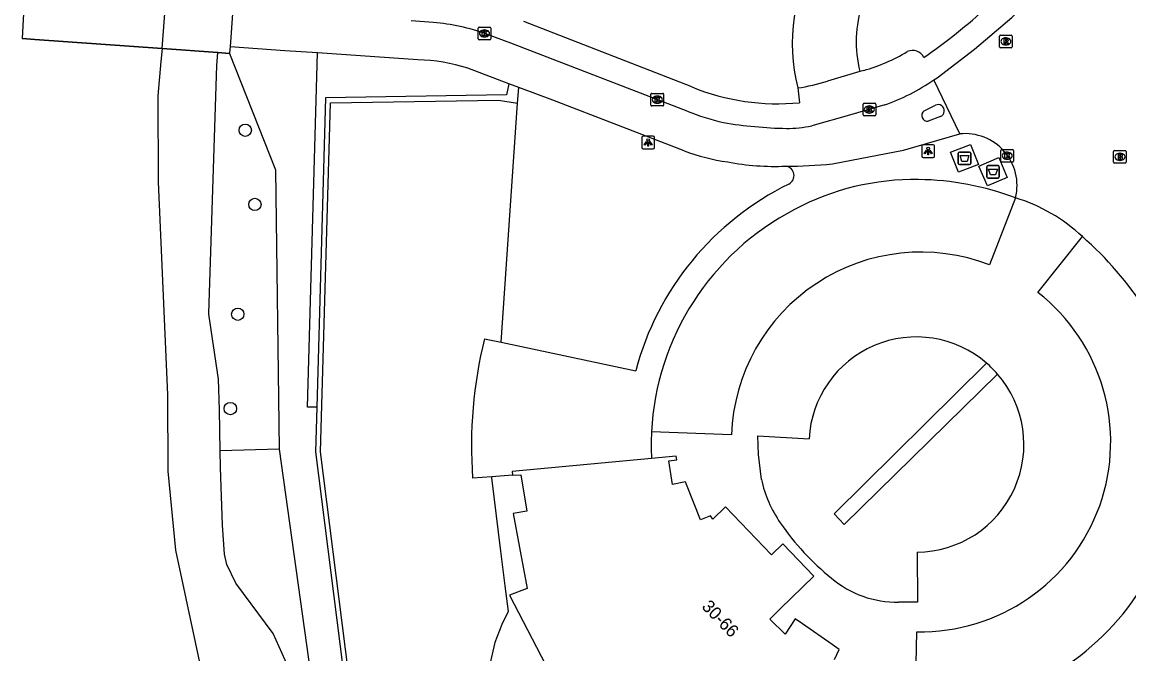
# Model space of a CAD drawing. Extents: x 159040 to 160094, y 381214 to 382518.
# Drawn here: x 159039.5 to 159127.2, y 381279.5 to 381329.5 of the extents above; entities that cross this region are included whole.
import ezdxf

# ---------------------------------------------------------------- set-up
doc = ezdxf.new("R2010")
doc.units = 0
for name, color, linetype in [('IMGEO_Afval_apart_plaats', 7, 'Continuous'), ('IMGEO_Boom', 7, 'Continuous'), ('IMGEO_Brandkraan', 7, 'Continuous'), ('IMGEO_Dek', 7, 'Continuous'), ('IMGEO_Fietspad_gesloten', 7, 'Continuous'), ('IMGEO_Fietspad_open', 7, 'Continuous'), ('IMGEO_Groenvoorziening', 7, 'Continuous'), ('IMGEO_Haag', 7, 'Continuous'), ('IMGEO_Hek', 7, 'Continuous'), ('IMGEO_Kolk', 7, 'Continuous'), ('IMGEO_Lichtpunt', 7, 'Continuous'), ('IMGEO_Pand', 7, 'Continuous'), ('IMGEO_Pand_nummerreeks', 7, 'Continuous'), ('IMGEO_Parkeervlak_open', 7, 'Continuous'), ('IMGEO_Rijbaan_lokaal_open', 7, 'Continuous'), ('IMGEO_Rioolput', 7, 'Continuous'), ('IMGEO_Voetpad_gesloten', 7, 'Continuous'), ('IMGEO_Voetpad_open', 7, 'Continuous'), ('IMGEO_Waterloop', 7, 'Continuous')]:
    doc.layers.add(name, color=color, linetype=linetype)

msp = doc.modelspace()

# ---------------------------------------------------------------- linework, layer by layer
at = {"layer": 'IMGEO_Afval_apart_plaats'}
for p, q in [((159113.713, 381318.326), (159113.713, 381319.126)), ((159113.713, 381319.126), (159113.713, 381318.326)), ((159113.813, 381319.226), (159114.603, 381319.226)), ((159114.603, 381319.226), (159113.813, 381319.226)), ((159114.703, 381319.126), (159114.703, 381318.326)), ((159114.703, 381318.326), (159114.703, 381319.126)), ((159114.603, 381318.226), (159113.813, 381318.226)), ((159113.813, 381318.226), (159114.603, 381318.226)), ((159115.976, 381317.265), (159115.976, 381318.065)), ((159115.976, 381318.065), (159115.976, 381317.265)), ((159116.076, 381318.165), (159116.866, 381318.165)), ((159116.866, 381318.165), (159116.076, 381318.165)), ((159116.966, 381318.065), (159116.966, 381317.265)), ((159116.966, 381317.265), (159116.966, 381318.065)), ((159116.866, 381317.165), (159116.076, 381317.165)), ((159116.076, 381317.165), (159116.866, 381317.165))]:
    msp.add_line(p, q, dxfattribs=at)
for points in [[(159113.856, 381318.94), (159114.56, 381318.94), (159114.411, 381318.47), (159114.005, 381318.47), (159113.856, 381318.94)], [(159116.119, 381317.879), (159116.823, 381317.879), (159116.674, 381317.409), (159116.268, 381317.409), (159116.119, 381317.879)]]:
    msp.add_lwpolyline(points, dxfattribs=at)
for centre, start, end in [((159113.813, 381319.126), 90, 180), ((159113.813, 381319.126), 90, 180), ((159114.603, 381319.126), 0, 90), ((159114.603, 381319.126), 360, 90), ((159113.813, 381318.326), 180, 270), ((159113.813, 381318.326), 180, 270), ((159114.603, 381318.326), 270, 0), ((159114.603, 381318.326), 270, 0), ((159116.076, 381318.065), 90, 180), ((159116.076, 381318.065), 90, 180), ((159116.866, 381318.065), 0, 90), ((159116.866, 381318.065), 360, 90), ((159116.076, 381317.265), 180, 270), ((159116.076, 381317.265), 180, 270), ((159116.866, 381317.265), 270, 0), ((159116.866, 381317.265), 270, 0)]:
    msp.add_arc(centre, 0.1, start, end, dxfattribs=at)
at = {"layer": 'IMGEO_Boom'}
for centre in [(159057.207, 381320.956), (159057.971, 381315.075), (159056.615, 381306.375), (159056.023, 381298.901)]:
    msp.add_circle(centre, 0.489, dxfattribs=at)
at = {"layer": 'IMGEO_Brandkraan'}
for p, q in [((159126.028, 381318.418), (159126.028, 381319.27)), ((159126.103, 381319.344), (159126.955, 381319.344)), ((159126.516, 381319.124), (159126.541, 381319.124)), ((159127.029, 381319.27), (159127.029, 381318.418)), ((159126.955, 381318.344), (159126.103, 381318.344)), ((159126.539, 381318.564), (159126.514, 381318.564))]:
    msp.add_line(p, q, dxfattribs=at)
for points in [[(159126.028, 381318.418), (159126.028, 381319.27)], [(159126.103, 381319.344), (159126.955, 381319.344)], [(159126.376, 381319.044), (159126.376, 381318.644), (159126.589, 381318.644)], [(159126.607, 381319.044), (159126.376, 381319.044)], [(159126.555, 381318.963), (159126.501, 381318.963), (159126.501, 381318.887)], [(159127.029, 381319.27), (159127.029, 381318.418)], [(159126.955, 381318.344), (159126.103, 381318.344)], [(159126.501, 381318.887), (159126.554, 381318.887)], [(159126.563, 381318.811), (159126.501, 381318.811), (159126.501, 381318.73)], [(159126.501, 381318.73), (159126.563, 381318.73)]]:
    msp.add_lwpolyline(points, dxfattribs=at)
for centre, radius, start, end in [((159126.105, 381319.268), 0.0765, 91.55205, 178.44795), ((159126.105, 381319.268), 0.0765, 91.55205, 178.44795), ((159126.556, 381318.925), 0.0379, 267.82845, 90.93552), ((159126.611, 381318.899), 0.145, 59.4692, 91.53667), ((159126.636, 381318.946), 0.0922, 285.51372, 58.15012), ((159126.953, 381319.268), 0.0765, 1.55205, 88.44795), ((159126.953, 381319.268), 0.0765, 1.55205, 88.44795), ((159126.105, 381318.42), 0.0765, 181.55205, 268.44795), ((159126.105, 381318.42), 0.0765, 181.55205, 268.44795), ((159126.564, 381318.77), 0.0404, 269.87594, 90.50774), ((159126.595, 381318.895), 0.251, 268.66757, 293.53466), ((159126.641, 381318.754), 0.105, 301.31148, 78.98903), ((159126.953, 381318.42), 0.0765, 271.55205, 358.44795), ((159126.953, 381318.42), 0.0765, 271.55205, 358.44795)]:
    msp.add_arc(centre, radius, start, end, dxfattribs=at)
for centre, major_axis, ratio, start_param, end_param in [((159126.515, 381318.844), (-0.387, 0.002), 0.722429, 4.712389, 7.853982), ((159126.54, 381318.844), (-0.39, 0.002), 0.717154, 1.570796, 4.712389)]:
    msp.add_ellipse(centre, major_axis=major_axis, ratio=ratio, start_param=start_param, end_param=end_param, dxfattribs=at)
at = {"layer": 'IMGEO_Dek'}
msp.add_lwpolyline([(159039.522, 381328.211), (159040.528, 381328.139), (159050.61, 381327.415), (159050.884, 381330.878), (159051.05, 381332.975), (159041.35, 381333.612), (159039.813, 381333.713)], close=True, dxfattribs=at)
at = {"layer": 'IMGEO_Fietspad_gesloten'}
for points in [[(159056.213, 381330.56), (159056.002, 381327.557)], [(159072.11, 381329.478), (159070.351, 381329.619)], [(159092.234, 381322.458), (159078.254, 381327.862), (159076.323, 381328.564)], [(159062.942, 381327.072), (159060.335, 381327.254), (159056.002, 381327.557)], [(159070.882, 381326.518), (159062.942, 381327.072)], [(159078.098, 381324.639), (159074.845, 381325.858)], [(159078.875, 381324.348), (159078.098, 381324.639)], [(159091.996, 381319.311), (159081.582, 381323.334), (159078.875, 381324.348)], [(159107.881, 381322.952), (159105.106, 381322.135), (159102.101, 381321.307)], [(159111.006, 381322.488), (159111.903, 381322.937)], [(159112.303, 381322.03), (159111.34, 381321.673)], [(159103.746, 381318.292), (159103.883, 381318.313), (159109.374, 381319.367), (159113.837, 381320.659)]]:
    msp.add_lwpolyline(points, dxfattribs=at)
for centre, radius, start, end in [((159071.003, 381314.209), 15.309, 69.66557, 85.85345), ((159070.726, 381313.351), 13.168, 71.76989, 89.31953), ((159102.403, 381338.407), 16.397, 289.51725, 304.82163), ((159099.562, 381340.778), 19.731, 248.19782, 256.95343), ((159111.27, 381322.12), 0.453, 125.6821, 278.8871), ((159112.113, 381322.488), 0.496, 292.59622, 115.00011), ((159100.793, 381356.007), 34.917, 260.62895, 268.85376), ((159100.161, 381330.154), 9.057, 269.58337, 282.36922), ((159097.909, 381335.419), 17.159, 249.84291, 261.74079), ((159099.198, 381338.512), 20.422, 259.40818, 272.33536), ((159100.221, 381351.676), 33.569, 269.67333, 276.02687)]:
    msp.add_arc(centre, radius, start, end, dxfattribs=at)
at = {"layer": 'IMGEO_Fietspad_open'}
for points in [[(159050.61, 381327.415), (159050.884, 381330.878)], [(159055.038, 381327.097), (159050.61, 381327.415)], [(159055.965, 381327.03), (159055.038, 381327.097)], [(159056.002, 381327.557), (159055.968, 381327.077), (159055.965, 381327.03)]]:
    msp.add_lwpolyline(points, dxfattribs=at)
at = {"layer": 'IMGEO_Groenvoorziening'}
for points in [[(159055.225, 381295.548), (159055.17, 381298.792), (159055.072, 381301.237), (159054.306, 381306.385), (159054.307, 381306.436), (159054.944, 381326.09), (159055.038, 381327.097)], [(159055.965, 381327.03), (159059.596, 381317.823), (159059.886, 381295.701)], [(159062.871, 381299.017), (159062.144, 381299.013), (159062.942, 381327.072)], [(159077.474, 381304.155), (159078.788, 381323.092)], [(159059.886, 381295.701), (159055.225, 381295.548)], [(159064.372, 381231.439), (159063.173, 381244.5), (159063.456, 381245.743), (159064.371, 381248.141), (159064.814, 381250.033), (159064.541, 381252.253), (159063.389, 381262.097), (159061.869, 381273.046), (159060.845, 381277.924), (159059.418, 381281.101), (159056.47, 381285.076), (159055.747, 381286.553), (159055.558, 381287.374), (159055.393, 381289.669), (159055.248, 381294.247), (159055.225, 381295.548)], [(159059.886, 381295.701), (159069.218, 381228.972)], [(159076.735, 381293.506), (159076.728, 381293.411), (159077.446, 381287.606), (159077.786, 381284.859), (159078.036, 381282.835), (159077.536, 381281.814), (159076.998, 381280.371), (159076.605, 381278.761), (159076.401, 381276.883), (159076.43, 381275.338), (159076.767, 381273.19), (159077.261, 381271.58), (159077.809, 381270.321), (159078.666, 381268.84), (159079.964, 381267.184), (159084.27, 381233.151)]]:
    msp.add_lwpolyline(points, dxfattribs=at)
at = {"layer": 'IMGEO_Haag'}
for points in [[(159078.098, 381324.639), (159077.92, 381323.747), (159063.568, 381323.527), (159062.871, 381299.017)], [(159078.788, 381323.092), (159078.875, 381324.348)], [(159084.27, 381233.151), (159071.09, 381232.965), (159063.171, 381295.487), (159063.957, 381323.133), (159077.281, 381323.321), (159078.788, 381323.092)], [(159062.871, 381299.017), (159062.77, 381295.468), (159070.738, 381232.56), (159071.355, 381232.569)]]:
    msp.add_lwpolyline(points, dxfattribs=at)
at = {"layer": 'IMGEO_Hek'}
for points in [[(159040.528, 381328.139), (159039.522, 381328.211)], [(159050.61, 381327.415), (159040.528, 381328.139)], [(159050.61, 381327.415), (159055.038, 381327.097)], [(159055.038, 381327.097), (159055.965, 381327.03)]]:
    msp.add_lwpolyline(points, dxfattribs=at)
at = {"layer": 'IMGEO_Kolk'}
for p, q in [((159075.663, 381328.195), (159075.663, 381329.047)), ((159075.738, 381329.121), (159076.59, 381329.121)), ((159076.151, 381328.901), (159076.176, 381328.901)), ((159076.664, 381329.047), (159076.664, 381328.195)), ((159076.59, 381328.121), (159075.738, 381328.121)), ((159076.174, 381328.341), (159076.149, 381328.341)), ((159089.361, 381322.948), (159089.361, 381323.8)), ((159089.436, 381323.874), (159090.288, 381323.874)), ((159089.849, 381323.654), (159089.874, 381323.654)), ((159090.362, 381323.8), (159090.362, 381322.948)), ((159090.288, 381322.874), (159089.436, 381322.874)), ((159089.872, 381323.094), (159089.847, 381323.094)), ((159106.168, 381322.168), (159106.168, 381323.02)), ((159106.243, 381323.094), (159107.095, 381323.094)), ((159106.656, 381322.874), (159106.681, 381322.874)), ((159107.169, 381323.02), (159107.169, 381322.168)), ((159107.095, 381322.094), (159106.243, 381322.094)), ((159106.679, 381322.314), (159106.654, 381322.314)), ((159117.095, 381318.506), (159117.095, 381319.358)), ((159117.17, 381319.432), (159118.022, 381319.432)), ((159117.583, 381319.212), (159117.608, 381319.212)), ((159118.096, 381319.358), (159118.096, 381318.506)), ((159118.022, 381318.432), (159117.17, 381318.432)), ((159117.606, 381318.652), (159117.581, 381318.652))]:
    msp.add_line(p, q, dxfattribs=at)
for points in [[(159075.663, 381328.195), (159075.663, 381329.047)], [(159075.738, 381329.121), (159076.59, 381329.121)], [(159075.984, 381328.821), (159076.107, 381328.821), (159076.107, 381328.67), (159076.237, 381328.821), (159076.401, 381328.821), (159076.255, 381328.67), (159076.408, 381328.421), (159076.256, 381328.421), (159076.171, 381328.585), (159076.107, 381328.518), (159076.107, 381328.421), (159075.984, 381328.421), (159075.984, 381328.821)], [(159076.664, 381329.047), (159076.664, 381328.195)], [(159076.59, 381328.121), (159075.738, 381328.121)], [(159089.361, 381322.948), (159089.361, 381323.8)], [(159089.436, 381323.874), (159090.288, 381323.874)], [(159089.682, 381323.574), (159089.805, 381323.574), (159089.805, 381323.423), (159089.935, 381323.574), (159090.099, 381323.574), (159089.953, 381323.423), (159090.106, 381323.174), (159089.954, 381323.174), (159089.869, 381323.338), (159089.805, 381323.271), (159089.805, 381323.174), (159089.682, 381323.174), (159089.682, 381323.574)], [(159090.362, 381323.8), (159090.362, 381322.948)], [(159090.288, 381322.874), (159089.436, 381322.874)], [(159106.168, 381322.168), (159106.168, 381323.02)], [(159106.243, 381323.094), (159107.095, 381323.094)], [(159106.489, 381322.794), (159106.612, 381322.794), (159106.612, 381322.643), (159106.742, 381322.794), (159106.906, 381322.794), (159106.76, 381322.643), (159106.913, 381322.394), (159106.761, 381322.394), (159106.676, 381322.558), (159106.612, 381322.491), (159106.612, 381322.394), (159106.489, 381322.394), (159106.489, 381322.794)], [(159107.169, 381323.02), (159107.169, 381322.168)], [(159107.095, 381322.094), (159106.243, 381322.094)], [(159117.095, 381318.506), (159117.095, 381319.358)], [(159117.17, 381319.432), (159118.022, 381319.432)], [(159117.416, 381319.132), (159117.539, 381319.132), (159117.539, 381318.981), (159117.669, 381319.132), (159117.833, 381319.132), (159117.687, 381318.981), (159117.84, 381318.732), (159117.688, 381318.732), (159117.603, 381318.896), (159117.539, 381318.829), (159117.539, 381318.732), (159117.416, 381318.732), (159117.416, 381319.132)], [(159118.096, 381319.358), (159118.096, 381318.506)], [(159118.022, 381318.432), (159117.17, 381318.432)]]:
    msp.add_lwpolyline(points, dxfattribs=at)
for centre, start, end in [((159075.74, 381329.045), 91.55205, 178.44795), ((159075.74, 381329.045), 91.55205, 178.44795), ((159076.588, 381329.045), 1.55205, 88.44795), ((159076.588, 381329.045), 1.55205, 88.44795), ((159075.74, 381328.197), 181.55205, 268.44795), ((159075.74, 381328.197), 181.55205, 268.44795), ((159076.588, 381328.197), 271.55205, 358.44795), ((159076.588, 381328.197), 271.55205, 358.44795), ((159089.438, 381323.798), 91.55205, 178.44795), ((159089.438, 381323.798), 91.55205, 178.44795), ((159090.286, 381323.798), 1.55205, 88.44795), ((159090.286, 381323.798), 1.55205, 88.44795), ((159089.438, 381322.95), 181.55205, 268.44795), ((159089.438, 381322.95), 181.55205, 268.44795), ((159090.286, 381322.95), 271.55205, 358.44795), ((159090.286, 381322.95), 271.55205, 358.44795), ((159106.245, 381323.018), 91.55205, 178.44795), ((159106.245, 381323.018), 91.55205, 178.44795), ((159107.093, 381323.018), 1.55205, 88.44795), ((159107.093, 381323.018), 1.55205, 88.44795), ((159106.245, 381322.17), 181.55205, 268.44795), ((159106.245, 381322.17), 181.55205, 268.44795), ((159107.093, 381322.17), 271.55205, 358.44795), ((159107.093, 381322.17), 271.55205, 358.44795), ((159117.172, 381319.356), 91.55205, 178.44795), ((159117.172, 381319.356), 91.55205, 178.44795), ((159118.02, 381319.356), 1.55205, 88.44795), ((159118.02, 381319.356), 1.55205, 88.44795), ((159117.172, 381318.508), 181.55205, 268.44795), ((159117.172, 381318.508), 181.55205, 268.44795), ((159118.02, 381318.508), 271.55205, 358.44795), ((159118.02, 381318.508), 271.55205, 358.44795)]:
    msp.add_arc(centre, 0.0765, start, end, dxfattribs=at)
for centre, major_axis, ratio, start_param, end_param in [((159076.15, 381328.621), (-0.387, 0.002), 0.722429, 4.712389, 7.853982), ((159076.175, 381328.621), (-0.39, 0.002), 0.717154, 1.570796, 4.712389), ((159089.848, 381323.374), (-0.387, 0.002), 0.722429, 4.712389, 7.853982), ((159089.873, 381323.374), (-0.39, 0.002), 0.717154, 1.570796, 4.712389), ((159106.655, 381322.594), (-0.387, 0.002), 0.722429, 4.712389, 7.853982), ((159106.68, 381322.594), (-0.39, 0.002), 0.717154, 1.570796, 4.712389), ((159117.582, 381318.932), (-0.387, 0.002), 0.722429, 4.712389, 7.853982), ((159117.607, 381318.932), (-0.39, 0.002), 0.717154, 1.570796, 4.712389)]:
    msp.add_ellipse(centre, major_axis=major_axis, ratio=ratio, start_param=start_param, end_param=end_param, dxfattribs=at)
at = {"layer": 'IMGEO_Lichtpunt'}
for p, q in [((159088.639, 381320.384), (159088.639, 381319.577)), ((159088.639, 381320.384), (159088.639, 381319.577)), ((159089.541, 381320.479), (159088.733, 381320.479)), ((159089.541, 381320.479), (159088.733, 381320.479)), ((159089.635, 381319.577), (159089.635, 381320.384)), ((159089.635, 381319.577), (159089.635, 381320.384)), ((159111.729, 381319.799), (159110.921, 381319.799)), ((159111.729, 381319.799), (159110.921, 381319.799)), ((159088.733, 381319.483), (159089.541, 381319.483)), ((159088.733, 381319.483), (159089.541, 381319.483)), ((159110.827, 381319.704), (159110.827, 381318.897)), ((159110.827, 381319.704), (159110.827, 381318.897)), ((159111.823, 381318.897), (159111.823, 381319.704)), ((159111.823, 381318.897), (159111.823, 381319.704)), ((159110.921, 381318.803), (159111.729, 381318.803)), ((159110.921, 381318.803), (159111.729, 381318.803))]:
    msp.add_line(p, q, dxfattribs=at)
for points in [[(159089.013, 381320.048), (159089.052, 381320.02), (159088.864, 381319.758), (159088.826, 381319.785), (159089.013, 381320.048)], [(159089.115, 381320), (159089.162, 381320), (159089.162, 381319.678), (159089.115, 381319.678), (159089.115, 381320)], [(159089.225, 381320.02), (159089.263, 381320.047), (159089.45, 381319.785), (159089.411, 381319.757), (159089.225, 381320.02)], [(159111.201, 381319.368), (159111.24, 381319.34), (159111.052, 381319.078), (159111.014, 381319.105), (159111.201, 381319.368)], [(159111.303, 381319.32), (159111.35, 381319.32), (159111.35, 381318.998), (159111.303, 381318.998), (159111.303, 381319.32)], [(159111.413, 381319.34), (159111.451, 381319.367), (159111.638, 381319.105), (159111.599, 381319.077), (159111.413, 381319.34)]]:
    msp.add_lwpolyline(points, dxfattribs=at)
for centre in [(159089.138, 381320.182), (159111.326, 381319.502)]:
    msp.add_circle(centre, 0.0994, dxfattribs=at)
for centre, start, end in [((159088.733, 381320.384), 90, 180), ((159088.733, 381320.384), 90, 180), ((159089.541, 381320.384), 0, 90), ((159089.541, 381320.384), 0, 90), ((159110.921, 381319.704), 90, 180), ((159110.921, 381319.704), 90, 180), ((159111.729, 381319.704), 0, 90), ((159111.729, 381319.704), 0, 90), ((159088.733, 381319.577), 180, 270), ((159088.733, 381319.577), 180, 270), ((159089.541, 381319.577), 270, 0), ((159089.541, 381319.577), 270, 360), ((159110.921, 381318.897), 180, 270), ((159110.921, 381318.897), 180, 270), ((159111.729, 381318.897), 270, 0), ((159111.729, 381318.897), 270, 360)]:
    msp.add_arc(centre, 0.0946, start, end, dxfattribs=at)
at = {"layer": 'IMGEO_Pand'}
for points in [[(159089.399, 381294.962), (159078.353, 381293.92), (159078.377, 381293.619)], [(159103.912, 381279.026), (159104.271, 381279.828), (159103.725, 381280.206), (159101.366, 381281.851), (159100.798, 381282.238), (159099.982, 381281.04), (159098.776, 381282.233), (159099.609, 381283.04), (159102.276, 381285.623), (159099.802, 381288.188), (159098.9, 381287.323), (159095.266, 381291.113), (159094.257, 381290.145), (159094.086, 381290.403), (159093.289, 381290.085), (159092.171, 381292.884), (159092.089, 381293.09), (159091.07, 381292.898), (159090.772, 381294.777), (159091.397, 381294.836), (159091.363, 381295.147), (159089.399, 381294.962)], [(159078.377, 381293.619), (159079.045, 381293.665), (159079.526, 381290.787), (159078.44, 381290.597), (159078.942, 381287.89), (159079.543, 381284.655), (159078.157, 381284.137), (159081.36, 381277.919)]]:
    msp.add_lwpolyline(points, dxfattribs=at)
at = {"layer": 'IMGEO_Parkeervlak_open'}
msp.add_lwpolyline([(159116.83, 381301.641), (159104.684, 381289.735), (159103.884, 381290.563), (159115.953, 381302.514)], dxfattribs=at)
msp.add_arc((159114.87, 381327.806), 14.316, 148.87936, 194.16654, dxfattribs=at)
at = {"layer": 'IMGEO_Rijbaan_lokaal_open'}
for points in [[(159111.766, 381324.946), (159112.05, 381325.112), (159115.003, 381327.379), (159117.946, 381329.878), (159121.211, 381333.268), (159121.837, 381333.996)], [(159106.217, 381325.687), (159105.909, 381325.597)], [(159113.837, 381320.659), (159111.766, 381324.946)], [(159118.256, 381315.598), (159116.195, 381310.283)], [(159120.019, 381308.11), (159123.554, 381312.524)], [(159095.732, 381296.818), (159089.402, 381297.051)], [(159098.11, 381293.297), (159097.872, 381295.274), (159097.832, 381296.74), (159101.889, 381296.519)], [(159110.455, 381287.537), (159110.483, 381283.563), (159108.99, 381283.572)], [(159110.294, 381274.904), (159110.432, 381281.231)]]:
    msp.add_lwpolyline(points, dxfattribs=at)
for centre, radius, start, end in [((159115.45, 381327.947), 9.826, 162.08941, 193.83803), ((159084.886, 381364.481), 45.91, 304.65715, 312.72893), ((159102.162, 381339.85), 14.732, 285.97602, 300.65699), ((159110.1, 381326.275), 0.997, 26.29348, 115.28117), ((159114.264, 381316.572), 4.109, 346.288, 95.96352), ((159114.249, 381302.59), 13.611, 46.87319, 72.88057), ((159105.314, 381291.727), 27.663, 32.79231, 48.74698), ((159110.758, 381296.264), 15.036, 68.8028, 177.88838), ((159110.758, 381296.264), 15.036, 268.75661, 51.98355), ((159110.395, 381296.058), 8.519, 49.27733, 176.89644), ((159108.091, 381293.739), 11.782, 42.12068, 48.14124), ((159110.397, 381296.056), 8.519, 270.38954, 40.96458), ((159110.779, 381295.976), 21.404, 177.12061, 182.71483), ((159107.772, 381295.456), 9.9, 192.5947, 214.45962), ((159116.502, 381301.451), 20.49, 214.4702, 231.24546), ((159108.842, 381291.542), 7.972, 229.59526, 271.06295)]:
    msp.add_arc(centre, radius, start, end, dxfattribs=at)
at = {"layer": 'IMGEO_Rioolput'}
for p, q in [((159116.988, 381327.562), (159116.988, 381328.414)), ((159117.063, 381328.488), (159117.915, 381328.488)), ((159117.499, 381327.708), (159117.474, 381327.708)), ((159117.476, 381328.268), (159117.501, 381328.268)), ((159117.989, 381328.414), (159117.989, 381327.562)), ((159117.915, 381327.488), (159117.063, 381327.488))]:
    msp.add_line(p, q, dxfattribs=at)
for points in [[(159116.988, 381327.562), (159116.988, 381328.414)], [(159117.063, 381328.488), (159117.915, 381328.488)], [(159117.577, 381328.186), (159117.325, 381328.188), (159117.325, 381327.788)], [(159117.325, 381327.788), (159117.449, 381327.788), (159117.449, 381327.95), (159117.46, 381327.95)], [(159117.503, 381328.107), (159117.449, 381328.107), (159117.449, 381328.026)], [(159117.449, 381328.026), (159117.501, 381328.026)], [(159117.507, 381327.921), (159117.578, 381327.788), (159117.718, 381327.788), (159117.653, 381327.914)], [(159117.989, 381328.414), (159117.989, 381327.562)], [(159117.915, 381327.488), (159117.063, 381327.488)]]:
    msp.add_lwpolyline(points, dxfattribs=at)
for centre, radius, start, end in [((159117.065, 381328.412), 0.0765, 91.55205, 178.44795), ((159117.065, 381328.412), 0.0765, 91.55205, 178.44795), ((159117.459, 381327.897), 0.0533, 26.02933, 88.69889), ((159117.485, 381328.215), 0.19, 274.7715, 282.96867), ((159117.509, 381328.011), 0.0964, 77.00612, 93.18647), ((159117.523, 381328.068), 0.0378, 276.66336, 79.67722), ((159117.576, 381328.076), 0.109, 350.36119, 89.41601), ((159117.574, 381328.076), 0.112, 277.58423, 350.98172), ((159117.558, 381327.861), 0.108, 29.51342, 73.79051), ((159117.913, 381328.412), 0.0765, 1.55205, 88.44795), ((159117.913, 381328.412), 0.0765, 1.55205, 88.44795), ((159117.065, 381327.564), 0.0765, 181.55205, 268.44795), ((159117.065, 381327.564), 0.0765, 181.55205, 268.44795), ((159117.913, 381327.564), 0.0765, 271.55205, 358.44795), ((159117.913, 381327.564), 0.0765, 271.55205, 358.44795)]:
    msp.add_arc(centre, radius, start, end, dxfattribs=at)
for centre, major_axis, ratio, start_param, end_param in [((159117.475, 381327.988), (-0.387, 0.002), 0.722429, 4.712389, 7.853982), ((159117.5, 381327.988), (-0.39, 0.002), 0.717154, 1.570796, 4.712389)]:
    msp.add_ellipse(centre, major_axis=major_axis, ratio=ratio, start_param=start_param, end_param=end_param, dxfattribs=at)
at = {"layer": 'IMGEO_Voetpad_gesloten'}
for points in [[(159113.105, 381319.208), (159114.68, 381319.833), (159115.311, 381318.244), (159113.736, 381317.619), (159113.105, 381319.208)], [(159115.352, 381318.113), (159116.922, 381318.783), (159117.591, 381317.216), (159116.021, 381316.546), (159115.352, 381318.113)]]:
    msp.add_lwpolyline(points, dxfattribs=at)
at = {"layer": 'IMGEO_Voetpad_open'}
for points in [[(159092.589, 381324.386), (159079.284, 381329.561)], [(159105.909, 381325.597), (159103.34, 381324.845)], [(159100.989, 381324.302), (159101.137, 381323.13)], [(159076.161, 381304.432), (159077.474, 381304.155)], [(159077.474, 381304.155), (159088.149, 381301.903)], [(159076.735, 381293.506), (159075.227, 381293.402)], [(159078.377, 381293.619), (159076.735, 381293.506)]]:
    msp.add_lwpolyline(points, dxfattribs=at)
for centre, radius, start, end in [((159099.395, 381340.993), 17.947, 247.71339, 275.56873), ((159099.008, 381338.239), 14.077, 278.08891, 287.92168), ((159099.953, 381317.361), 0.75, 296.13843, 84.14443), ((159110.442, 381295.977), 23.067, 116.12703, 165.11332), ((159110.247, 381296.797), 20.251, 89.08683, 118.01303), ((159110.25, 381294.207), 22.841, 69.4799, 89.19618), ((159110.447, 381295.973), 21.073, 117.44165, 177.06818), ((159110.435, 381295.975), 35.302, 166.13973, 184.17996), ((159110.446, 381295.974), 21.071, 269.5872, 12.02983)]:
    msp.add_arc(centre, radius, start, end, dxfattribs=at)
at = {"layer": 'IMGEO_Waterloop'}
msp.add_lwpolyline([(159050.61, 381327.415), (159050.515, 381326.395), (159050.283, 381323.67), (159050.292, 381316.862), (159051.051, 381300.002), (159051.07, 381293.955), (159051.681, 381287.684), (159054.049, 381276.569)], dxfattribs=at)

# ---------------------------------------------------------------- texts
at = {"layer": 'IMGEO_Pand_nummerreeks'}
msp.add_text('30-66', height=1, rotation=313.96284, dxfattribs=at).set_placement((159093.323, 381283.162))

doc.saveas('drawing.dxf')
